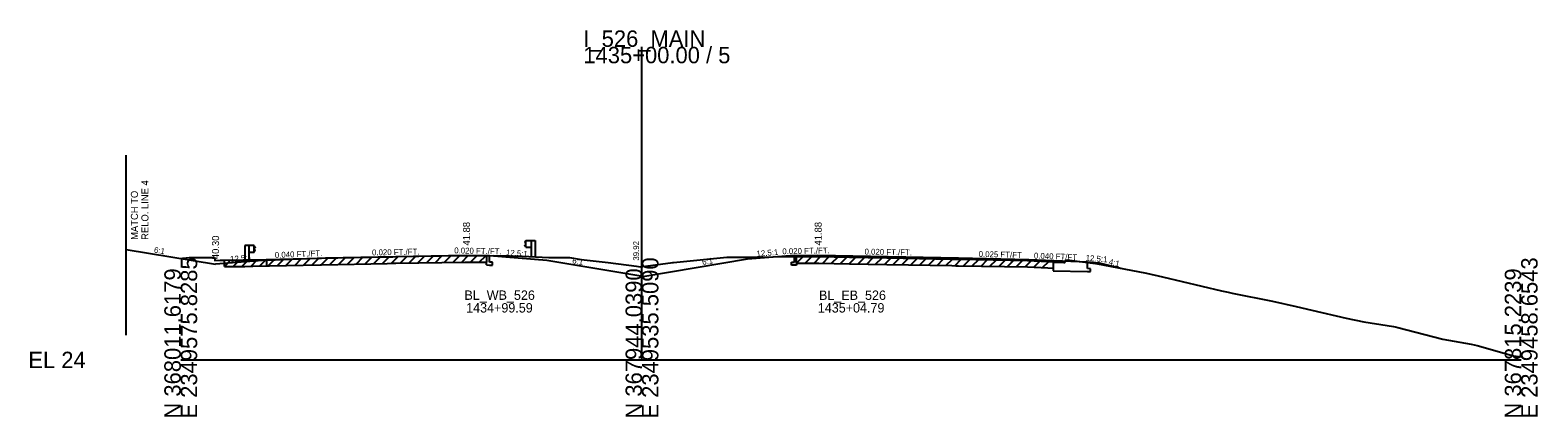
# Model space of a CAD drawing. Extents: x -170 to 2527928, y -10 to 1619750.
# Drawn here: x 4974.3 to 5231.5, y 1490.3 to 1556.2 of the extents above; entities that cross this region are included whole.
import ezdxf

# ---------------------------------------------------------------- set-up
doc = ezdxf.new("R2010")
doc.units = 0
for name, color, linetype in [('RD_GPK_XS_Cell', 7, 'Continuous'), ('RD_XS_Base', 7, 'Continuous'), ('RD_XS_EarthShd', 7, 'Continuous'), ('RD_XS_ExGround', 7, 'Continuous'), ('RD_XS_ExPaveRet', 7, 'Continuous'), ('RD_XS_GR', 7, 'Continuous'), ('RD_XS_MatchLine', 7, 'Continuous'), ('RD_XS_Pave', 7, 'Continuous'), ('RD_XS_PaveShd', 7, 'Continuous'), ('RD_XS_TieSlope', 7, 'Continuous'), ('RD_XS_TX_Elev_EX', 7, 'Continuous'), ('RD_XS_TX_Slope', 7, 'Continuous'), ('RD_XS_TX_Station', 7, 'Continuous')]:
    doc.layers.add(name, color=color, linetype=linetype)

msp = doc.modelspace()

# ---------------------------------------------------------------- linework, layer by layer
at = {"layer": 'RD_GPK_XS_Cell'}
for p, q in [((5078.69, 1500), (5078.69, 1553.36)), ((5000, 1500), (5078.69, 1500)), ((5078.69, 1500), (5228.69, 1500))]:
    msp.add_line(p, q, dxfattribs=at)
at = {"layer": 'RD_XS_Base'}
for p, q in [((5052.69, 1516.67), (5052.69, 1517.8)), ((5104.69, 1516.66), (5104.69, 1517.8)), ((5014.69, 1516.01), (5014.69, 1517)), ((5052.14, 1516.18), (5052.14, 1516.65)), ((5052.14, 1516.18), (5052.69, 1516.17)), ((5053.19, 1516.66), (5052.69, 1516.67)), ((5052.69, 1516.17), (5053.19, 1516.16)), ((5053.19, 1516.16), (5053.19, 1516.66)), ((5104.19, 1516.65), (5104.69, 1516.66)), ((5104.19, 1516.15), (5104.19, 1516.65)), ((5105.05, 1516.17), (5104.19, 1516.15)), ((5105.05, 1516.47), (5105.05, 1516.17)), ((5148.86, 1516.93), (5148.86, 1515.21)), ((5148.86, 1515.21), (5154.69, 1515.06)), ((5154.69, 1515.56), (5154.69, 1516.7)), ((5155.19, 1515.55), (5154.69, 1515.56)), ((5154.69, 1515.06), (5155.19, 1515.05)), ((5155.19, 1515.05), (5155.19, 1515.55))]:
    msp.add_line(p, q, dxfattribs=at)
at = {"layer": 'RD_XS_EarthShd'}
for p, q in [((5052.69, 1517.8), (5062.44, 1517.02)), ((5104.69, 1517.8), (5096.69, 1517.16)), ((5014.69, 1517), (5005.93, 1516.3))]:
    msp.add_line(p, q, dxfattribs=at)
at = {"layer": 'RD_XS_ExGround'}
msp.add_lwpolyline([(5000, 1517.28), (5000.38, 1517.35), (5001.43, 1517.46), (5005.31, 1517.43), (5005.48, 1517.42), (5005.74, 1517.41), (5005.8, 1517.12), (5005.84, 1516.93), (5006.7, 1516.99), (5007.23, 1517), (5007.36, 1517.03), (5007.44, 1517.03), (5010.65, 1517.04), (5010.93, 1517.05), (5012.29, 1517.08), (5023.81, 1517.34), (5023.91, 1517.34), (5024, 1517.34), (5035.24, 1517.57), (5036.16, 1517.59), (5036.71, 1517.6), (5048.46, 1517.79), (5051.09, 1517.78), (5052.14, 1517.77), (5053.36, 1517.78), (5058.26, 1517.7), (5062.77, 1517.47), (5066.31, 1517.43), (5068.3, 1517.12), (5072.91, 1516.63), (5077.78, 1515.96), (5078.45, 1515.88), (5083.93, 1516.59), (5083.96, 1516.59), (5083.99, 1516.59), (5084.07, 1516.6), (5093.17, 1517.51), (5093.63, 1517.52), (5099.4, 1517.5), (5102.61, 1517.61), (5105.05, 1517.59), (5107.19, 1517.61), (5108.88, 1517.64), (5114.1, 1517.52), (5120.48, 1517.39), (5131.56, 1517.19), (5132.25, 1517.18), (5132.67, 1517.17), (5144.46, 1516.97), (5147.91, 1516.8), (5148.86, 1516.77), (5148.87, 1516.76), (5149.02, 1516.68), (5150.69, 1516.61), (5150.82, 1516.6), (5150.98, 1517.01), (5150.99, 1517.03), (5151.37, 1517.04), (5151.39, 1517.04), (5151.61, 1517.01), (5156.09, 1516.42), (5157.3, 1516.2), (5164.74, 1514.79), (5167.47, 1514.15), (5177.54, 1511.79), (5178.39, 1511.6), (5178.68, 1511.55), (5179.38, 1511.38), (5186.29, 1510.04), (5190.28, 1509.11), (5192.96, 1508.49), (5198.85, 1507.14), (5201.85, 1506.52), (5205.85, 1505.88), (5206.91, 1505.71), (5207.17, 1505.64), (5207.64, 1505.53), (5215.3, 1503.54), (5220.13, 1502.69), (5221.16, 1502.48), (5227.37, 1500.69), (5228.69, 1500.55)], dxfattribs=at)
at = {"layer": 'RD_XS_ExPaveRet'}
for p, q in [((5037.44, 1516.49), (5038.57, 1517.63)), ((5038.94, 1516.52), (5040.07, 1517.65)), ((5040.44, 1516.54), (5041.57, 1517.68)), ((5041.94, 1516.56), (5043.07, 1517.7)), ((5043.44, 1516.59), (5044.57, 1517.72)), ((5044.94, 1516.61), (5046.07, 1517.75)), ((5046.44, 1516.63), (5047.57, 1517.77)), ((5047.94, 1516.66), (5049.06, 1517.78)), ((5049.44, 1516.66), (5050.56, 1517.78)), ((5050.94, 1516.66), (5052.05, 1517.77)), ((5052.14, 1517.77), (5052.14, 1516.65)), ((5007.44, 1515.91), (5008.56, 1517.04)), ((5007.44, 1515.91), (5007.44, 1517.03)), ((5007.44, 1515.91), (5010.65, 1515.92)), ((5008.94, 1515.92), (5010.06, 1517.04)), ((5010.44, 1515.92), (5011.58, 1517.06)), ((5010.65, 1515.92), (5010.93, 1515.93)), ((5010.93, 1515.93), (5012.29, 1515.96)), ((5011.94, 1515.95), (5013.08, 1517.09)), ((5012.29, 1515.96), (5023.81, 1516.22)), ((5013.44, 1515.98), (5014.58, 1517.13)), ((5014.94, 1516.02), (5016.08, 1517.16)), ((5016.44, 1516.05), (5017.58, 1517.2)), ((5017.94, 1516.08), (5019.08, 1517.23)), ((5019.44, 1516.12), (5020.58, 1517.27)), ((5020.94, 1516.15), (5022.08, 1517.3)), ((5022.44, 1516.19), (5023.58, 1517.34)), ((5023.81, 1516.22), (5024, 1516.22)), ((5023.94, 1516.22), (5025.08, 1517.36)), ((5024, 1516.22), (5035.24, 1516.45)), ((5025.44, 1516.25), (5026.58, 1517.39)), ((5026.94, 1516.28), (5028.08, 1517.43)), ((5028.44, 1516.31), (5029.58, 1517.46)), ((5029.94, 1516.34), (5031.08, 1517.49)), ((5031.44, 1516.37), (5032.58, 1517.52)), ((5032.94, 1516.41), (5034.08, 1517.55)), ((5034.44, 1516.44), (5035.58, 1517.58)), ((5035.24, 1516.45), (5036.16, 1516.47)), ((5035.94, 1516.47), (5037.08, 1517.61)), ((5036.16, 1516.47), (5036.71, 1516.48)), ((5036.71, 1516.48), (5048.46, 1516.66)), ((5048.46, 1516.66), (5051.09, 1516.66)), ((5051.09, 1516.66), (5052.14, 1516.65)), ((5105.05, 1516.47), (5106.18, 1517.6)), ((5105.05, 1516.47), (5105.05, 1517.59)), ((5105.05, 1516.47), (5107.19, 1516.49)), ((5106.55, 1516.48), (5107.68, 1517.62)), ((5107.19, 1516.49), (5108.88, 1516.51)), ((5108.05, 1516.5), (5109.17, 1517.63)), ((5108.88, 1516.51), (5114.1, 1516.4)), ((5109.55, 1516.5), (5110.65, 1517.6)), ((5111.05, 1516.47), (5112.15, 1517.56)), ((5112.55, 1516.43), (5113.65, 1517.53)), ((5114.05, 1516.4), (5115.15, 1517.5)), ((5114.1, 1516.4), (5120.48, 1516.26)), ((5115.55, 1516.37), (5116.65, 1517.47)), ((5117.05, 1516.34), (5118.15, 1517.43)), ((5118.55, 1516.31), (5119.65, 1517.4)), ((5120.05, 1516.27), (5121.15, 1517.37)), ((5120.48, 1516.26), (5131.56, 1516.07)), ((5121.55, 1516.25), (5122.65, 1517.35)), ((5123.05, 1516.22), (5124.15, 1517.32)), ((5124.55, 1516.19), (5125.65, 1517.29)), ((5126.05, 1516.16), (5127.15, 1517.27)), ((5127.55, 1516.14), (5128.65, 1517.24)), ((5129.05, 1516.11), (5130.15, 1517.21)), ((5130.55, 1516.08), (5131.65, 1517.19)), ((5131.56, 1516.07), (5132.25, 1516.05)), ((5132.05, 1516.06), (5133.15, 1517.16)), ((5132.25, 1516.05), (5132.67, 1516.05)), ((5132.67, 1516.05), (5144.46, 1515.85)), ((5133.55, 1516.03), (5134.65, 1517.14)), ((5135.05, 1516.01), (5136.15, 1517.11)), ((5136.55, 1515.98), (5137.65, 1517.09)), ((5138.05, 1515.96), (5139.15, 1517.06)), ((5139.55, 1515.93), (5140.65, 1517.03)), ((5141.05, 1515.91), (5142.15, 1517.01)), ((5142.55, 1515.88), (5143.65, 1516.98)), ((5144.05, 1515.86), (5145.13, 1516.94)), ((5144.46, 1515.85), (5147.91, 1515.68)), ((5145.55, 1515.8), (5146.62, 1516.87)), ((5147.05, 1515.73), (5148.12, 1516.8)), ((5147.91, 1515.68), (5148.86, 1515.65)), ((5148.86, 1516.77), (5148.86, 1515.65))]:
    msp.add_line(p, q, dxfattribs=at)
at = {"layer": 'RD_XS_GR'}
for p, q in [((5058.86, 1520.29), (5058.69, 1520.09)), ((5058.86, 1519.2), (5058.86, 1520.37)), ((5058.86, 1520.37), (5059.78, 1520.37)), ((5059.78, 1520.37), (5060.44, 1520.37)), ((5059.78, 1520.37), (5059.78, 1517.62)), ((5060.44, 1520.37), (5060.44, 1517.57)), ((5011.61, 1519.5), (5010.94, 1519.5)), ((5010.94, 1519.5), (5010.94, 1516.7)), ((5012.53, 1519.5), (5011.61, 1519.5)), ((5011.61, 1519.5), (5011.61, 1516.76)), ((5012.53, 1518.33), (5011.61, 1518.33)), ((5012.53, 1518.33), (5012.53, 1519.5)), ((5012.53, 1519.43), (5012.69, 1519.23)), ((5012.69, 1519.18), (5012.53, 1518.98)), ((5012.69, 1518.66), (5012.53, 1518.86)), ((5012.53, 1518.41), (5012.69, 1518.61)), ((5012.69, 1519.23), (5012.69, 1519.18)), ((5012.69, 1518.61), (5012.69, 1518.66)), ((5058.69, 1520.09), (5058.69, 1520.04)), ((5058.69, 1520.04), (5058.86, 1519.84)), ((5058.69, 1519.52), (5058.86, 1519.72)), ((5058.69, 1519.47), (5058.69, 1519.52)), ((5058.86, 1519.27), (5058.69, 1519.47)), ((5058.86, 1519.2), (5059.78, 1519.2))]:
    msp.add_line(p, q, dxfattribs=at)
at = {"layer": 'RD_XS_MatchLine'}
msp.add_line((4990.69, 1504.23), (4990.69, 1534.9), dxfattribs=at)
msp.add_line((4990.69, 1504.23), (4990.69, 1534.9), dxfattribs=at)
msp.add_line((4990.69, 1504.23), (4990.69, 1534.9), dxfattribs=at)
at = {"layer": 'RD_XS_Pave'}
for p, q in [((5024.69, 1517.4), (5048.69, 1517.88)), ((5108.69, 1517.88), (5132.69, 1517.4)), ((5132.69, 1517.4), (5144.69, 1517.1))]:
    msp.add_line(p, q, dxfattribs=at)
at = {"layer": 'RD_XS_PaveShd'}
for p, q in [((5048.69, 1517.88), (5052.69, 1517.8)), ((5104.69, 1517.8), (5108.69, 1517.88)), ((5014.69, 1517), (5024.69, 1517.4)), ((5144.69, 1517.1), (5154.69, 1516.7))]:
    msp.add_line(p, q, dxfattribs=at)
at = {"layer": 'RD_XS_TieSlope'}
for p, q in [((4990.69, 1518.84), (5005.93, 1516.3)), ((5062.44, 1517.02), (5079.16, 1514.24)), ((5096.69, 1517.16), (5079.16, 1514.24)), ((5154.69, 1516.7), (5156.69, 1516.54)), ((5156.69, 1516.54), (5160.38, 1515.62))]:
    msp.add_line(p, q, dxfattribs=at)

# ---------------------------------------------------------------- texts
at = {"layer": 'RD_GPK_XS_Cell'}
for s, p in [('I_526_MAIN', (5068.69, 1553.36)), ('1435+00.00 / 5', (5068.69, 1550.56)), ('EL 24', (4974, 1498.6))]:
    msp.add_text(s, height=2.8, dxfattribs=at).set_placement(p)
for s, p in [('N 368011.6179', (5000, 1490)), ('E 2349575.8285', (5002.8, 1490)), ('N 367944.0390', (5078.69, 1490)), ('E 2349535.5090', (5081.49, 1490)), ('N 367815.2239', (5228.69, 1490)), ('E 2349458.6543', (5231.49, 1490))]:
    msp.add_text(s, height=2.8, rotation=90, dxfattribs=at).set_placement(p)
at = {"layer": 'RD_XS_TX_Elev_EX'}
msp.add_text('39.92', height=1, rotation=90, dxfattribs=at).set_placement((5078.19, 1516.92))
at = {"layer": 'RD_XS_TX_Slope'}
for s, rotation, p in [('6:1', 350.5377, (4995.38, 1518.3)), ('12.5:1', 4.5739, (5008.47, 1516.68)), ('0.040 FT./FT.', 2.2906, (5016.07, 1517.37)), ('0.020 FT./FT.', 1.1458, (5032.64, 1517.81)), ('0.020 FT./FT.', 358.8542, (5046.65, 1518.17)), ('12.5:1', 355.4261, (5055.45, 1517.84)), ('12.5:1', 4.5739, (5098.27, 1517.6)), ('0.020 FT./FT.', 1.1458, (5102.64, 1518.01)), ('0.020 FT./FT.', 358.8542, (5116.65, 1517.97)), ('0.025 FT/FT', 358.5679, (5136.12, 1517.56)), ('0.040 FT/FT', 357.7094, (5145.54, 1517.29)), ('12.5:1', 355.4261, (5154.36, 1516.92)), ('6:1', 350.5377, (5066.74, 1516.47)), ('6:1', 9.4623, (5089.03, 1516.17)), ('4:1', 346.8379, (5158.25, 1516.28))]:
    msp.add_text(s, height=1, rotation=rotation, dxfattribs=at).set_placement(p)
at = {"layer": 'RD_XS_TX_Station'}
for s, p in [('RELO. LINE 4', (4994.49, 1520.46)), ('MATCH TO', (4992.69, 1520.46)), (' 41.88', (5049.35, 1519.05)), (' 41.88', (5109.35, 1519.05)), ('40.30', (5006.54, 1517.18))]:
    msp.add_text(s, height=1.2, rotation=90, dxfattribs=at).set_placement(p)
for s, p in [('BL_WB_526', (5048.4, 1510.24)), ('BL_EB_526', (5108.89, 1510.23)), ('1434+99.59', (5048.69, 1508.08)), ('1435+04.79', (5108.69, 1508.08))]:
    msp.add_text(s, height=1.6, dxfattribs=at).set_placement(p)

doc.saveas('drawing.dxf')
